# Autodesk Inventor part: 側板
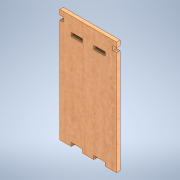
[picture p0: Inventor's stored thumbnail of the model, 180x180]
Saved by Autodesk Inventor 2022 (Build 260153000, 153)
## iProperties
Created: 2024-11
Part Number: 側板
Material: MDF 中密度繊維ボード
Document SubType Name: Modeling
Designer: shimizu
Density: 0.8 g/cm^3
Appearance: サクラ材 - ナチュラル 抑えた光沢
Author: shimizu
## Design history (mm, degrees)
sketch "スケッチ1"
  geometry: L1 (-20.243, 58.107)-(19.757, 58.107); L2 (-4.243, -21.893)-(-4.243, -19.393); L3 (-4.243, -19.393)-(-12.243, -19.393); L4 (-12.243, -19.393)-(-12.243, -21.893); L5 (11.757, -21.893)-(11.757, -19.393); L6 (11.757, -19.393)-(3.757, -19.393); L7 (3.757, -19.393)-(3.757, -21.893); L8 (-12.243, 48.107)-(-4.243, 48.107); L9 (-4.243, 48.107)-(-4.243, 45.607); L10 (-4.243, 45.607)-(-12.243, 45.607); L11 (-12.243, 45.607)-(-12.243, 48.107); L12 (3.757, 48.107)-(11.757, 48.107); L13 (11.757, 48.107)-(11.757, 45.607); L14 (11.757, 45.607)-(3.757, 45.607); L15 (3.757, 45.607)-(3.757, 48.107); L16 (-12.243, -21.893)-(-20.243, -21.893); L17 (19.757, -21.893)-(11.757, -21.893); L18 (3.757, -21.893)-(-4.243, -21.893); L19 (-20.243, 54.607)-(-17.743, 54.607); L20 (-17.743, 54.607)-(-17.743, 51.607); L21 (-17.743, 51.607)-(-20.243, 51.607); L22 (19.757, 54.607)-(17.257, 54.607); L23 (17.257, 54.607)-(17.257, 51.607); L24 (17.257, 51.607)-(19.757, 51.607); L25 (-20.243, -21.893)-(-20.243, 51.607); L26 (-20.243, 54.607)-(-20.243, 58.107); L27 (19.757, 58.107)-(19.757, 54.607); L28 (19.757, 51.607)-(19.757, -21.893); 1 further point
  constraints: 56 end point, 15 parallel, 6 perpendicular, 5 horizontal
extrude "押し出し1" new body sketch "スケッチ1" distance "d13" = 2.5; taper "d14" = 0 deg
node "ソリッド1"
